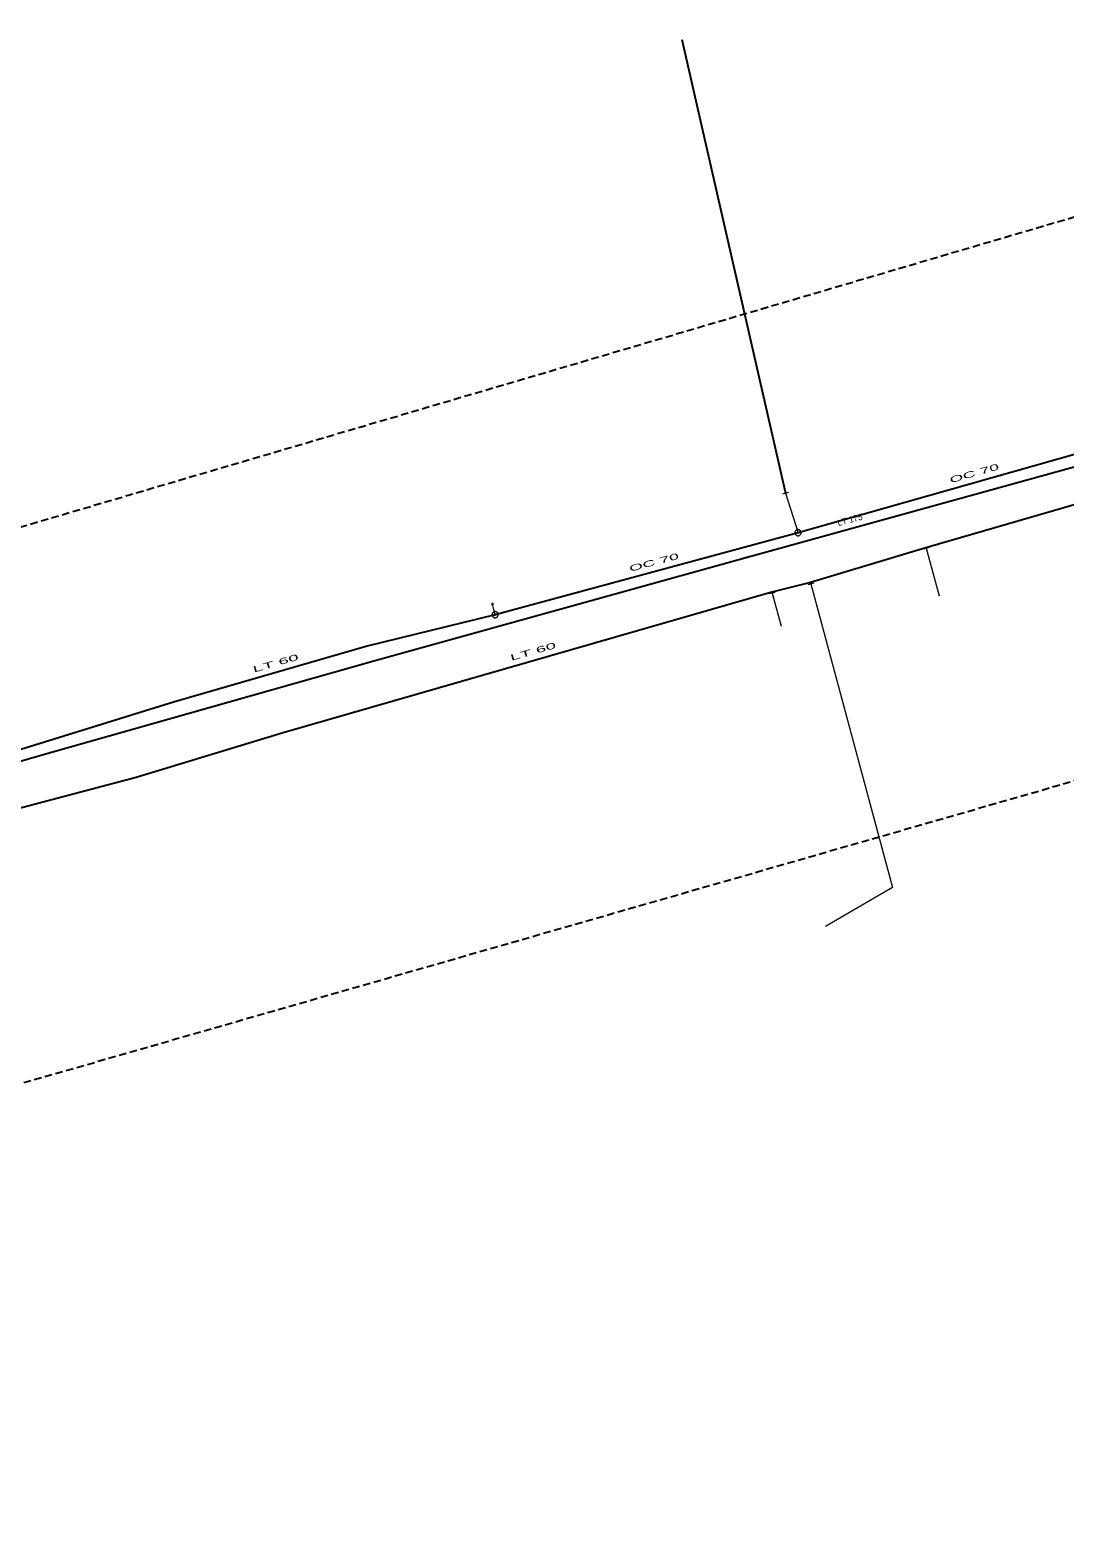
# Model space of a CAD drawing. Extents: x -690254 to -689100, y -975264 to -974703.
# Drawn here: x -689916.6 to -689747.9, y -975238.2 to -974992.3 of the extents above; entities that cross this region are included whole.
import ezdxf

# ---------------------------------------------------------------- set-up
doc = ezdxf.new("R2010")
doc.units = 0
doc.header["$LTSCALE"] = 0.4
doc.linetypes.add('MEDIUM_DASHED', pattern=[4.5, 3, -1.5])
for name, color, linetype, lineweight in [('1', 7, 'Continuous', 13), ('13', 7, 'Continuous', 13), ('14', 7, 'Continuous', 13), ('17', 7, 'Continuous', 25), ('34', 7, 'Continuous', 13), ('47', 7, 'Continuous', 13), ('63', 7, 'MEDIUM_DASHED', 25), ('9', 7, 'Continuous', 13)]:
    doc.layers.add(name, color=color, linetype=linetype, lineweight=lineweight)

msp = doc.modelspace()

# ---------------------------------------------------------------- linework, layer by layer
at = {"layer": '13'}
for p, q in [((-689770.502, -975076.787), (-689768.367, -975084.52)), ((-689795.619, -975084.105), (-689794.159, -975089.511))]:
    msp.add_line(p, q, dxfattribs=at)
msp.add_lwpolyline([(-689789.301, -975082.593), (-689775.982, -975132.122), (-689786.936, -975138.472)], dxfattribs=at)
at = {"layer": '14'}
for p, q in [((-689793.458, -975067.822), (-689791.401, -975074.243)), ((-689800.052, -975078.399), (-689800.079, -975078.309)), ((-689770.531, -975076.689), (-689770.502, -975076.787)), ((-689789.368, -975082.372), (-689789.301, -975082.593)), ((-689840.799, -975087.611), (-689841.229, -975085.908)), ((-689795.659, -975083.946), (-689795.619, -975084.105)), ((-689860.597, -975095.177), (-689860.62, -975095.1)), ((-689913.514, -975110.178), (-689913.539, -975110.1))]:
    msp.add_line(p, q, dxfattribs=at)
at = {"layer": '17'}
for p, q in [((-689736.277, -975058.649), (-689791.401, -975074.243)), ((-689791.401, -975074.243), (-689840.799, -975087.611))]:
    msp.add_line(p, q, dxfattribs=at)
for points in [[(-689810.37, -974993.835), (-689803.785, -975022.629), (-689793.458, -975067.822)], [(-689651.896, -975035.605), (-689702.719, -975051.484), (-689800.052, -975078.399), (-689860.597, -975095.177), (-689913.514, -975110.178), (-689937.55, -975117.079), (-689948.793, -975119.833), (-689957.109, -975122.39), (-689986.109, -975129.956), (-690002.122, -975134.99), (-690005.949, -975136.193), (-690003.879, -975142.529), (-690036.781, -975151.448), (-690069.227, -975161.229), (-690080.424, -975165.129), (-690111.773, -975174.27), (-690115.204, -975175.288), (-690118.142, -975167.265)], [(-689654.548, -975043.14), (-689663.456, -975045.689), (-689770.531, -975076.689), (-689789.368, -975082.372), (-689795.659, -975083.946), (-689875.347, -975106.869), (-689899.317, -975114.153), (-689955.443, -975128.986), (-689982.052, -975137.931), (-690059.236, -975159.265)], [(-689840.799, -975087.611), (-689861.691, -975092.768), (-689893.267, -975101.86), (-689919.753, -975110.091)]]:
    msp.add_lwpolyline(points, dxfattribs=at)
at = {"layer": '34'}
for p, q in [((-689792.97, -975067.71), (-689793.945, -975067.932)), ((-689799.598, -975078.17), (-689800.559, -975078.446)), ((-689770.023, -975076.642), (-689770.98, -975076.931)), ((-689788.822, -975082.448), (-689789.779, -975082.736)), ((-689795.134, -975083.981), (-689796.103, -975084.227)), ((-689861.099, -975095.241), (-689860.14, -975094.959)), ((-689914.014, -975110.255), (-689913.063, -975109.945))]:
    msp.add_line(p, q, dxfattribs=at)
at = {"layer": '47'}
for points in [[(-689790.916, -975074.12), (-689790.932, -975074.07), (-689790.952, -975074.021), (-689790.978, -975073.976), (-689791.007, -975073.933), (-689791.042, -975073.894), (-689791.081, -975073.858), (-689791.123, -975073.828), (-689791.168, -975073.801), (-689791.215, -975073.779), (-689791.265, -975073.761), (-689791.316, -975073.75), (-689791.368, -975073.744), (-689791.42, -975073.743), (-689791.472, -975073.748), (-689791.523, -975073.758), (-689791.573, -975073.774), (-689791.622, -975073.794), (-689791.668, -975073.82), (-689791.71, -975073.849), (-689791.749, -975073.884), (-689791.785, -975073.923), (-689791.816, -975073.965), (-689791.843, -975074.01), (-689791.865, -975074.057), (-689791.882, -975074.107), (-689791.893, -975074.158), (-689791.9, -975074.21), (-689791.9, -975074.262), (-689791.895, -975074.314), (-689791.885, -975074.365), (-689791.869, -975074.415), (-689791.849, -975074.464), (-689791.824, -975074.51), (-689791.794, -975074.552), (-689791.759, -975074.591), (-689791.721, -975074.627), (-689791.679, -975074.659), (-689791.634, -975074.685), (-689791.586, -975074.707), (-689791.536, -975074.724), (-689791.485, -975074.735), (-689791.434, -975074.742), (-689791.381, -975074.742), (-689791.329, -975074.737), (-689791.278, -975074.727), (-689791.228, -975074.711), (-689791.179, -975074.691), (-689791.134, -975074.666), (-689791.091, -975074.636), (-689791.052, -975074.601), (-689791.016, -975074.563), (-689790.985, -975074.521), (-689790.959, -975074.476), (-689790.937, -975074.428), (-689790.919, -975074.378), (-689790.908, -975074.327), (-689790.902, -975074.276), (-689790.901, -975074.223), (-689790.906, -975074.171)], [(-689791.321, -975074.222), (-689791.323, -975074.214), (-689791.327, -975074.206), (-689791.331, -975074.199), (-689791.336, -975074.192), (-689791.342, -975074.185), (-689791.348, -975074.18), (-689791.355, -975074.174), (-689791.362, -975074.17), (-689791.37, -975074.167), (-689791.378, -975074.164), (-689791.387, -975074.162), (-689791.395, -975074.161), (-689791.404, -975074.161), (-689791.412, -975074.161), (-689791.421, -975074.163), (-689791.429, -975074.165), (-689791.437, -975074.169), (-689791.444, -975074.173), (-689791.451, -975074.178), (-689791.458, -975074.184), (-689791.463, -975074.19), (-689791.469, -975074.197), (-689791.473, -975074.204), (-689791.477, -975074.212), (-689791.479, -975074.22), (-689791.481, -975074.229), (-689791.482, -975074.237), (-689791.482, -975074.246), (-689791.482, -975074.254), (-689791.48, -975074.263), (-689791.478, -975074.271), (-689791.474, -975074.279), (-689791.47, -975074.286), (-689791.465, -975074.293), (-689791.459, -975074.3), (-689791.454, -975074.306), (-689791.446, -975074.311), (-689791.439, -975074.315), (-689791.431, -975074.319), (-689791.423, -975074.321), (-689791.414, -975074.323), (-689791.406, -975074.324), (-689791.397, -975074.324), (-689791.389, -975074.324), (-689791.38, -975074.322), (-689791.372, -975074.32), (-689791.364, -975074.316), (-689791.357, -975074.312), (-689791.35, -975074.307), (-689791.343, -975074.301), (-689791.337, -975074.296), (-689791.332, -975074.288), (-689791.328, -975074.281), (-689791.325, -975074.273), (-689791.322, -975074.265), (-689791.32, -975074.256), (-689791.319, -975074.248), (-689791.319, -975074.239), (-689791.319, -975074.231)], [(-689840.314, -975087.488), (-689840.33, -975087.438), (-689840.35, -975087.389), (-689840.376, -975087.344), (-689840.405, -975087.301), (-689840.44, -975087.262), (-689840.479, -975087.226), (-689840.521, -975087.196), (-689840.566, -975087.169), (-689840.613, -975087.147), (-689840.663, -975087.129), (-689840.714, -975087.118), (-689840.766, -975087.112), (-689840.818, -975087.111), (-689840.87, -975087.116), (-689840.921, -975087.126), (-689840.971, -975087.142), (-689841.02, -975087.162), (-689841.066, -975087.188), (-689841.108, -975087.217), (-689841.147, -975087.252), (-689841.183, -975087.291), (-689841.214, -975087.333), (-689841.241, -975087.378), (-689841.263, -975087.425), (-689841.28, -975087.475), (-689841.291, -975087.526), (-689841.298, -975087.578), (-689841.298, -975087.63), (-689841.293, -975087.682), (-689841.283, -975087.733), (-689841.267, -975087.783), (-689841.247, -975087.832), (-689841.222, -975087.878), (-689841.192, -975087.92), (-689841.157, -975087.959), (-689841.119, -975087.995), (-689841.077, -975088.027), (-689841.032, -975088.053), (-689840.984, -975088.075), (-689840.934, -975088.092), (-689840.883, -975088.103), (-689840.832, -975088.11), (-689840.779, -975088.11), (-689840.727, -975088.105), (-689840.676, -975088.095), (-689840.626, -975088.079), (-689840.577, -975088.059), (-689840.532, -975088.034), (-689840.489, -975088.004), (-689840.45, -975087.969), (-689840.414, -975087.931), (-689840.383, -975087.889), (-689840.357, -975087.844), (-689840.335, -975087.796), (-689840.317, -975087.746), (-689840.306, -975087.695), (-689840.3, -975087.644), (-689840.299, -975087.591), (-689840.304, -975087.539)], [(-689840.719, -975087.59), (-689840.721, -975087.582), (-689840.725, -975087.574), (-689840.729, -975087.567), (-689840.734, -975087.56), (-689840.74, -975087.553), (-689840.746, -975087.548), (-689840.753, -975087.542), (-689840.76, -975087.538), (-689840.768, -975087.535), (-689840.776, -975087.532), (-689840.785, -975087.53), (-689840.793, -975087.529), (-689840.802, -975087.529), (-689840.81, -975087.529), (-689840.819, -975087.531), (-689840.827, -975087.533), (-689840.835, -975087.537), (-689840.842, -975087.541), (-689840.849, -975087.546), (-689840.856, -975087.552), (-689840.861, -975087.558), (-689840.867, -975087.565), (-689840.871, -975087.572), (-689840.875, -975087.58), (-689840.877, -975087.588), (-689840.879, -975087.597), (-689840.88, -975087.605), (-689840.88, -975087.614), (-689840.88, -975087.622), (-689840.878, -975087.631), (-689840.876, -975087.639), (-689840.872, -975087.647), (-689840.868, -975087.654), (-689840.863, -975087.661), (-689840.857, -975087.668), (-689840.852, -975087.674), (-689840.844, -975087.679), (-689840.837, -975087.683), (-689840.829, -975087.687), (-689840.821, -975087.689), (-689840.812, -975087.691), (-689840.804, -975087.692), (-689840.795, -975087.692), (-689840.787, -975087.692), (-689840.778, -975087.69), (-689840.77, -975087.688), (-689840.762, -975087.684), (-689840.755, -975087.68), (-689840.748, -975087.675), (-689840.741, -975087.669), (-689840.735, -975087.664), (-689840.73, -975087.656), (-689840.726, -975087.649), (-689840.723, -975087.641), (-689840.72, -975087.633), (-689840.718, -975087.624), (-689840.717, -975087.616), (-689840.717, -975087.607), (-689840.717, -975087.599)]]:
    msp.add_lwpolyline(points, close=True, dxfattribs=at)
at = {"layer": '63'}
msp.add_lwpolyline([(-690175.832, -975238.167), (-690201.511, -975156.663), (-690201.511, -975156.663), (-689696.859, -975008.171), (-689696.859, -975008.171), (-689730.354, -974917.735), (-689730.354, -974917.735), (-689127.452, -974763.66), (-689127.452, -974763.66), (-689118.52, -974838.465), (-689118.52, -974838.465), (-689624.288, -974970.21), (-689624.288, -974970.21), (-689593.026, -975070.694), (-689593.026, -975070.694)], close=True, dxfattribs=at)
at = {"layer": '9'}
for points in [[(-689841.355, -975085.908), (-689841.355, -975085.921), (-689841.353, -975085.934), (-689841.35, -975085.947), (-689841.345, -975085.959), (-689841.339, -975085.971), (-689841.332, -975085.982), (-689841.324, -975085.992), (-689841.314, -975086.002), (-689841.304, -975086.01), (-689841.293, -975086.017), (-689841.281, -975086.023), (-689841.269, -975086.028), (-689841.256, -975086.031), (-689841.243, -975086.033), (-689841.23, -975086.035), (-689841.217, -975086.034), (-689841.204, -975086.032), (-689841.191, -975086.029), (-689841.179, -975086.024), (-689841.167, -975086.018), (-689841.156, -975086.011), (-689841.146, -975086.003), (-689841.136, -975085.993), (-689841.128, -975085.983), (-689841.121, -975085.972), (-689841.115, -975085.96), (-689841.11, -975085.948), (-689841.107, -975085.935), (-689841.105, -975085.922), (-689841.103, -975085.909), (-689841.104, -975085.896), (-689841.106, -975085.883), (-689841.109, -975085.87), (-689841.114, -975085.858), (-689841.12, -975085.846), (-689841.127, -975085.835), (-689841.135, -975085.825), (-689841.145, -975085.815), (-689841.155, -975085.807), (-689841.166, -975085.8), (-689841.178, -975085.794), (-689841.19, -975085.789), (-689841.203, -975085.786), (-689841.216, -975085.784), (-689841.229, -975085.783), (-689841.242, -975085.783), (-689841.255, -975085.785), (-689841.268, -975085.788), (-689841.28, -975085.793), (-689841.292, -975085.799), (-689841.303, -975085.806), (-689841.313, -975085.814), (-689841.323, -975085.824), (-689841.331, -975085.834), (-689841.338, -975085.845), (-689841.344, -975085.857), (-689841.349, -975085.869), (-689841.352, -975085.882), (-689841.354, -975085.895)], [(-689841.335, -975085.908), (-689841.336, -975085.919), (-689841.334, -975085.93), (-689841.331, -975085.941), (-689841.327, -975085.951), (-689841.322, -975085.961), (-689841.316, -975085.97), (-689841.309, -975085.979), (-689841.301, -975085.987), (-689841.292, -975085.994), (-689841.283, -975086), (-689841.273, -975086.005), (-689841.263, -975086.009), (-689841.252, -975086.012), (-689841.241, -975086.015), (-689841.23, -975086.015), (-689841.219, -975086.015), (-689841.208, -975086.013), (-689841.197, -975086.01), (-689841.187, -975086.006), (-689841.177, -975086.001), (-689841.168, -975085.995), (-689841.159, -975085.988), (-689841.151, -975085.98), (-689841.144, -975085.971), (-689841.138, -975085.962), (-689841.133, -975085.952), (-689841.129, -975085.942), (-689841.126, -975085.931), (-689841.124, -975085.92), (-689841.123, -975085.909), (-689841.123, -975085.898), (-689841.125, -975085.887), (-689841.128, -975085.876), (-689841.132, -975085.866), (-689841.137, -975085.856), (-689841.143, -975085.847), (-689841.15, -975085.838), (-689841.158, -975085.83), (-689841.167, -975085.823), (-689841.176, -975085.817), (-689841.186, -975085.812), (-689841.196, -975085.808), (-689841.207, -975085.805), (-689841.218, -975085.803), (-689841.229, -975085.803), (-689841.24, -975085.802), (-689841.251, -975085.804), (-689841.262, -975085.807), (-689841.272, -975085.811), (-689841.282, -975085.816), (-689841.291, -975085.822), (-689841.3, -975085.829), (-689841.308, -975085.837), (-689841.315, -975085.846), (-689841.321, -975085.855), (-689841.326, -975085.865), (-689841.33, -975085.875), (-689841.333, -975085.886), (-689841.335, -975085.897)], [(-689841.316, -975085.908), (-689841.316, -975085.917), (-689841.315, -975085.926), (-689841.312, -975085.935), (-689841.309, -975085.943), (-689841.305, -975085.951), (-689841.3, -975085.959), (-689841.294, -975085.966), (-689841.288, -975085.972), (-689841.281, -975085.978), (-689841.273, -975085.983), (-689841.265, -975085.987), (-689841.257, -975085.99), (-689841.248, -975085.993), (-689841.239, -975085.994), (-689841.23, -975085.996), (-689841.221, -975085.995), (-689841.212, -975085.994), (-689841.203, -975085.991), (-689841.195, -975085.988), (-689841.187, -975085.984), (-689841.179, -975085.979), (-689841.172, -975085.973), (-689841.166, -975085.967), (-689841.16, -975085.96), (-689841.155, -975085.952), (-689841.151, -975085.944), (-689841.148, -975085.936), (-689841.145, -975085.927), (-689841.144, -975085.918), (-689841.142, -975085.909), (-689841.143, -975085.9), (-689841.144, -975085.891), (-689841.147, -975085.882), (-689841.15, -975085.874), (-689841.154, -975085.866), (-689841.159, -975085.858), (-689841.165, -975085.851), (-689841.171, -975085.845), (-689841.178, -975085.839), (-689841.186, -975085.834), (-689841.194, -975085.83), (-689841.202, -975085.827), (-689841.211, -975085.824), (-689841.22, -975085.823), (-689841.229, -975085.822), (-689841.238, -975085.822), (-689841.247, -975085.823), (-689841.256, -975085.826), (-689841.264, -975085.829), (-689841.272, -975085.833), (-689841.28, -975085.838), (-689841.287, -975085.844), (-689841.293, -975085.85), (-689841.299, -975085.857), (-689841.304, -975085.865), (-689841.308, -975085.873), (-689841.311, -975085.881), (-689841.314, -975085.89), (-689841.315, -975085.899)], [(-689841.296, -975085.908), (-689841.296, -975085.915), (-689841.295, -975085.922), (-689841.294, -975085.929), (-689841.291, -975085.935), (-689841.288, -975085.941), (-689841.284, -975085.947), (-689841.28, -975085.953), (-689841.275, -975085.958), (-689841.269, -975085.962), (-689841.263, -975085.966), (-689841.257, -975085.969), (-689841.251, -975085.972), (-689841.244, -975085.973), (-689841.237, -975085.976), (-689841.23, -975085.976), (-689841.223, -975085.976), (-689841.216, -975085.974), (-689841.209, -975085.973), (-689841.203, -975085.97), (-689841.196, -975085.967), (-689841.191, -975085.963), (-689841.185, -975085.959), (-689841.18, -975085.954), (-689841.176, -975085.948), (-689841.172, -975085.942), (-689841.169, -975085.936), (-689841.166, -975085.93), (-689841.164, -975085.923), (-689841.163, -975085.916), (-689841.162, -975085.909), (-689841.162, -975085.902), (-689841.163, -975085.895), (-689841.165, -975085.888), (-689841.168, -975085.882), (-689841.171, -975085.875), (-689841.175, -975085.87), (-689841.179, -975085.864), (-689841.184, -975085.859), (-689841.19, -975085.855), (-689841.195, -975085.851), (-689841.202, -975085.848), (-689841.208, -975085.845), (-689841.215, -975085.843), (-689841.222, -975085.842), (-689841.229, -975085.842), (-689841.236, -975085.842), (-689841.243, -975085.842), (-689841.25, -975085.844), (-689841.256, -975085.847), (-689841.262, -975085.85), (-689841.268, -975085.854), (-689841.274, -975085.858), (-689841.279, -975085.863), (-689841.283, -975085.869), (-689841.287, -975085.874), (-689841.29, -975085.881), (-689841.293, -975085.887), (-689841.294, -975085.894), (-689841.296, -975085.901)], [(-689841.276, -975085.908), (-689841.276, -975085.913), (-689841.276, -975085.918), (-689841.275, -975085.923), (-689841.273, -975085.927), (-689841.271, -975085.932), (-689841.268, -975085.936), (-689841.265, -975085.939), (-689841.261, -975085.943), (-689841.258, -975085.946), (-689841.254, -975085.949), (-689841.249, -975085.951), (-689841.245, -975085.953), (-689841.24, -975085.954), (-689841.235, -975085.956), (-689841.23, -975085.956), (-689841.225, -975085.956), (-689841.22, -975085.955), (-689841.215, -975085.954), (-689841.211, -975085.952), (-689841.206, -975085.95), (-689841.202, -975085.947), (-689841.198, -975085.944), (-689841.195, -975085.94), (-689841.192, -975085.937), (-689841.189, -975085.933), (-689841.187, -975085.928), (-689841.185, -975085.924), (-689841.184, -975085.919), (-689841.183, -975085.914), (-689841.182, -975085.909), (-689841.182, -975085.904), (-689841.183, -975085.899), (-689841.184, -975085.894), (-689841.186, -975085.89), (-689841.188, -975085.885), (-689841.191, -975085.881), (-689841.194, -975085.877), (-689841.197, -975085.874), (-689841.201, -975085.871), (-689841.205, -975085.868), (-689841.21, -975085.866), (-689841.214, -975085.864), (-689841.219, -975085.863), (-689841.224, -975085.862), (-689841.229, -975085.862), (-689841.234, -975085.862), (-689841.239, -975085.863), (-689841.244, -975085.863), (-689841.248, -975085.865), (-689841.253, -975085.867), (-689841.257, -975085.87), (-689841.26, -975085.873), (-689841.264, -975085.876), (-689841.267, -975085.88), (-689841.27, -975085.884), (-689841.272, -975085.889), (-689841.274, -975085.893), (-689841.275, -975085.898), (-689841.276, -975085.903)], [(-689841.256, -975085.908), (-689841.256, -975085.911), (-689841.257, -975085.914), (-689841.256, -975085.916), (-689841.255, -975085.919), (-689841.254, -975085.922), (-689841.252, -975085.924), (-689841.25, -975085.926), (-689841.248, -975085.928), (-689841.246, -975085.93), (-689841.244, -975085.932), (-689841.241, -975085.934), (-689841.238, -975085.935), (-689841.236, -975085.935), (-689841.233, -975085.936), (-689841.23, -975085.936), (-689841.227, -975085.936), (-689841.224, -975085.936), (-689841.221, -975085.935), (-689841.219, -975085.934), (-689841.216, -975085.933), (-689841.214, -975085.931), (-689841.211, -975085.929), (-689841.209, -975085.927), (-689841.208, -975085.925), (-689841.206, -975085.923), (-689841.205, -975085.92), (-689841.203, -975085.917), (-689841.203, -975085.915), (-689841.202, -975085.912), (-689841.201, -975085.909), (-689841.202, -975085.906), (-689841.202, -975085.903), (-689841.203, -975085.9), (-689841.204, -975085.898), (-689841.205, -975085.895), (-689841.207, -975085.893), (-689841.208, -975085.89), (-689841.21, -975085.888), (-689841.213, -975085.887), (-689841.215, -975085.885), (-689841.218, -975085.884), (-689841.22, -975085.883), (-689841.223, -975085.882), (-689841.226, -975085.882), (-689841.229, -975085.881), (-689841.232, -975085.882), (-689841.235, -975085.881), (-689841.237, -975085.883), (-689841.24, -975085.883), (-689841.243, -975085.884), (-689841.245, -975085.886), (-689841.247, -975085.887), (-689841.249, -975085.889), (-689841.251, -975085.892), (-689841.253, -975085.894), (-689841.254, -975085.897), (-689841.255, -975085.899), (-689841.256, -975085.902), (-689841.256, -975085.905)], [(-689841.237, -975085.908), (-689841.237, -975085.91), (-689841.237, -975085.91), (-689841.236, -975085.91), (-689841.236, -975085.912), (-689841.237, -975085.913), (-689841.235, -975085.913), (-689841.235, -975085.913), (-689841.235, -975085.915), (-689841.235, -975085.915), (-689841.234, -975085.916), (-689841.232, -975085.916), (-689841.232, -975085.916), (-689841.232, -975085.917), (-689841.23, -975085.917), (-689841.23, -975085.917), (-689841.229, -975085.917), (-689841.228, -975085.917), (-689841.228, -975085.916), (-689841.227, -975085.916), (-689841.225, -975085.916), (-689841.225, -975085.915), (-689841.225, -975085.915), (-689841.224, -975085.914), (-689841.224, -975085.914), (-689841.222, -975085.913), (-689841.222, -975085.912), (-689841.221, -975085.911), (-689841.221, -975085.911), (-689841.221, -975085.91), (-689841.221, -975085.909), (-689841.221, -975085.908), (-689841.221, -975085.907), (-689841.221, -975085.907), (-689841.222, -975085.906), (-689841.222, -975085.905), (-689841.223, -975085.904), (-689841.223, -975085.904), (-689841.224, -975085.903), (-689841.224, -975085.903), (-689841.225, -975085.902), (-689841.226, -975085.902), (-689841.227, -975085.901), (-689841.227, -975085.901), (-689841.228, -975085.901), (-689841.229, -975085.901), (-689841.23, -975085.901), (-689841.231, -975085.901), (-689841.231, -975085.901), (-689841.232, -975085.902), (-689841.233, -975085.901), (-689841.234, -975085.903), (-689841.234, -975085.903), (-689841.235, -975085.903), (-689841.235, -975085.903), (-689841.236, -975085.905), (-689841.236, -975085.906), (-689841.236, -975085.907), (-689841.237, -975085.907), (-689841.237, -975085.908)]]:
    msp.add_lwpolyline(points, close=True, dxfattribs=at)

# ---------------------------------------------------------------- texts
at = {"layer": '1'}
for s, rotation, width, p in [('OC 70 ', 16, 2.15, (-689766.512, -975066.178)), ('OC 70 ', 15, 2.15, (-689818.77, -975080.628)), ('LT 60 ', 16, 2.25, (-689838.178, -975095.151)), ('LT 60 ', 16, 2.25, (-689880.154, -975097.059))]:
    msp.add_text(s, height=1, rotation=rotation, dxfattribs=dict(at, width=width)).set_placement(p)
msp.add_text('LT 175', height=1, rotation=15, dxfattribs=at).set_placement((-689784.817, -975073.161))

doc.saveas('drawing.dxf')
